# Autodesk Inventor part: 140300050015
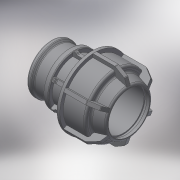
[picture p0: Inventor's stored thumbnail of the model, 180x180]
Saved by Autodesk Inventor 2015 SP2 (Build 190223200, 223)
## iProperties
Created: 2017-08
Part Number: 140300050015
Material: Generic
Description: PLASSON L.14 FEMALE ADAPTOR (SILVER) 50-1.1/2"
Document SubType Name: Modeling
Designer: KIM
Density: 1 g/cm^3
Appearance: Default
Author: KIM
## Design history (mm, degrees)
derived "140300.ipt"
feature "Solid1::140300.ipt"
tag "TaggingFeature1"
body "Solid1"
other parameters: "d2" = 82, "d4" = 15 deg, "d5" = 54.12, "d6" = 17.8596, "d9" = 44.845, "d10" = 92, "d11" = 58.2985, "d12" = 53.814, "d13" = 62.783, "d14" = 25, "d16" = 51, "d17" = 4.1, "d18" = 107, "d19" = 7.5, "d20" = 135 deg, "d21" = 7.5, "d22" = 53.814, "d23" = 45, "d24" = 4.1, "d25" = 82.8, "d26" = 69, "d27" = 4.1, "d28" = 135 deg, "d29" = 2.46, "d31" = 2.5, "d44" = 1, "d45" = 1.5, "d46" = 150 deg, "d49" = 4.6, "d50" = 0, "d51" = 0.92, "d52" = 1.84, "d53" = 45 deg, "d55" = 10.052, "d56" = 4.6, "d57" = 0, "d58" = 1.5, "d61" = 360 deg, "G_" = 44.845, "E_" = 92, "H_" = 107, "l_" = 82, "l_2" = 25, "d54" = 25.13
